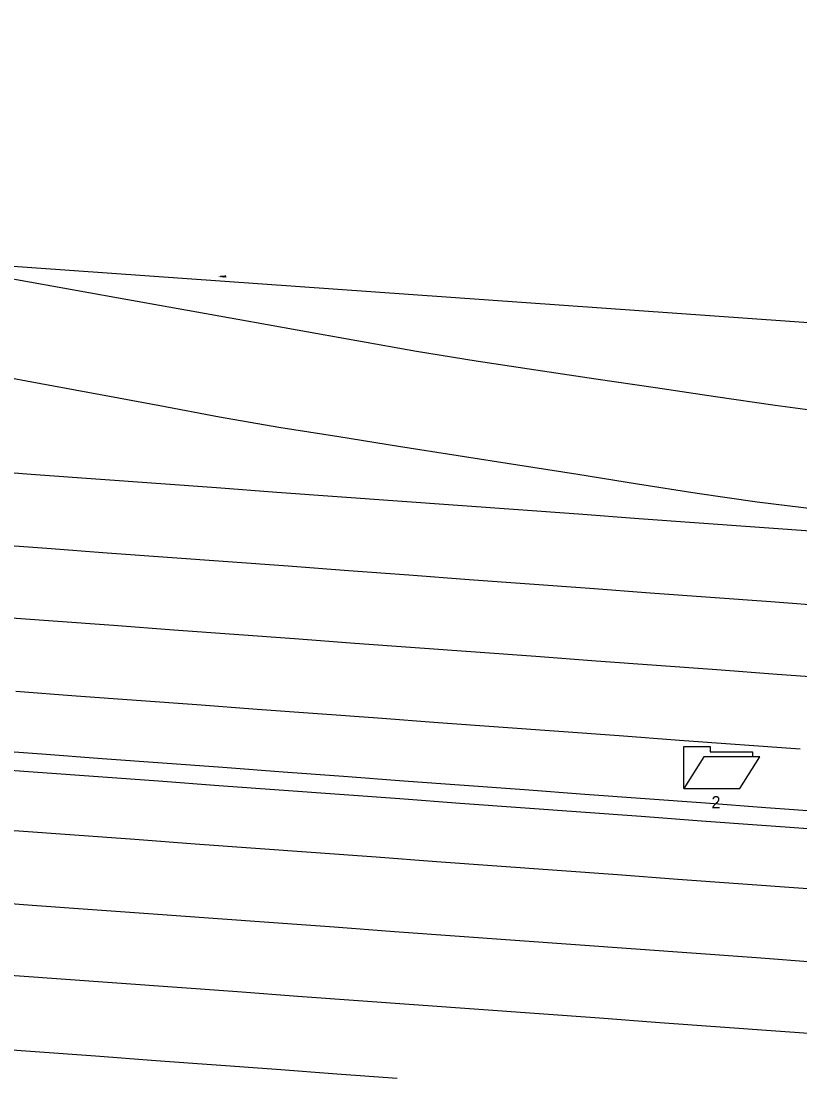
# Model space of a CAD drawing. Extents: x 1981993 to 1984113, y 708143 to 709490.
# Drawn here: x 1982674.4 to 1982803.2, y 708893.5 to 709067.8 of the extents above; entities that cross this region are included whole.
import ezdxf

# ---------------------------------------------------------------- set-up
doc = ezdxf.new("R2010")
doc.units = 0
for name, color, linetype in [('GE_X_Alignment_1000_Curve_Data', 7, 'Continuous'), ('GE_X_Alignment_1000_Distances', 7, 'Continuous'), ('GE_X_Alignment_100_Curve_Data', 7, 'Continuous'), ('GE_X_Alignment_100_Distances', 7, 'Continuous'), ('GE_X_Alignment_100_Stations', 7, 'Continuous'), ('GE_X_Alignment_500_Bearings', 7, 'Continuous'), ('GE_X_Alignment_500_Cardinal_Points', 7, 'Continuous'), ('GE_X_Alignment_500_Distances', 7, 'Continuous'), ('Scan Positions', 7, 'Continuous'), ('SV_P_Control_Cells_Set', 7, 'Continuous'), ('XS_X_Ground_Line', 7, 'Continuous')]:
    doc.layers.add(name, color=color, linetype=linetype)

msp = doc.modelspace()

# ---------------------------------------------------------------- linework, layer by layer
at = {"layer": 'GE_X_Alignment_1000_Curve_Data'}
for points in [[(1982808.34, 708971.06), (1982798.37, 708971.79), (1982788.4, 708972.53), (1982778.42, 708973.26), (1982768.45, 708973.99), (1982758.48, 708974.73), (1982748.5, 708975.46), (1982738.53, 708976.2), (1982728.56, 708976.93), (1982718.58, 708977.67), (1982708.61, 708978.4), (1982698.64, 708979.13), (1982688.67, 708979.87), (1982678.69, 708980.6), (1982668.72, 708981.34)], [(1982809.35, 708959.09), (1982799.38, 708959.82), (1982789.41, 708960.55), (1982779.44, 708961.28), (1982769.46, 708962.01), (1982759.49, 708962.75), (1982749.52, 708963.48), (1982739.54, 708964.21), (1982729.57, 708964.94), (1982719.6, 708965.67), (1982709.62, 708966.41), (1982699.65, 708967.14), (1982689.68, 708967.87), (1982679.7, 708968.6), (1982669.73, 708969.33)], [(1982666.31, 708922.44), (1982676.28, 708921.71), (1982686.25, 708920.99), (1982696.23, 708920.26), (1982706.2, 708919.54), (1982716.17, 708918.81), (1982726.15, 708918.09), (1982736.12, 708917.36), (1982746.1, 708916.64), (1982756.07, 708915.91), (1982766.04, 708915.19), (1982776.02, 708914.46), (1982785.99, 708913.74), (1982795.96, 708913.02), (1982805.94, 708912.29)], [(1982670.29, 708910.3), (1982680.27, 708909.58), (1982690.24, 708908.85), (1982700.21, 708908.13), (1982710.19, 708907.4), (1982720.16, 708906.68), (1982730.13, 708905.95), (1982740.11, 708905.23), (1982750.08, 708904.5), (1982760.05, 708903.78), (1982770.03, 708903.05), (1982780, 708902.33), (1982789.98, 708901.6), (1982799.95, 708900.88), (1982809.92, 708900.15)]]:
    msp.add_lwpolyline(points, dxfattribs=at)
at = {"layer": 'GE_X_Alignment_100_Curve_Data'}
msp.add_line((1982707.46, 709025.56), (1982707.46, 709025.56), dxfattribs=at)
for points in [[(1982707.67, 709025.48), (1982707.67, 709025.64), (1982707.72, 709025.48), (1982707.77, 709025.64), (1982707.77, 709025.48)], [(1982707.85, 709025.51), (1982707.85, 709025.51), (1982707.86, 709025.5), (1982707.86, 709025.5), (1982707.86, 709025.49), (1982707.86, 709025.49), (1982707.85, 709025.48), (1982707.85, 709025.48), (1982707.84, 709025.49), (1982707.84, 709025.49), (1982707.84, 709025.5), (1982707.84, 709025.5), (1982707.85, 709025.51)], [(1982707.91, 709025.48), (1982707.91, 709025.64), (1982707.99, 709025.48), (1982707.99, 709025.64)], [(1982708.07, 709025.51), (1982708.07, 709025.51), (1982708.08, 709025.5), (1982708.08, 709025.5), (1982708.08, 709025.49), (1982708.08, 709025.49), (1982708.07, 709025.48), (1982708.07, 709025.48), (1982708.06, 709025.49), (1982708.06, 709025.49), (1982708.06, 709025.5), (1982708.06, 709025.5), (1982708.07, 709025.51)], [(1982708.2, 709025.63), (1982708.2, 709025.64), (1982708.2, 709025.64), (1982708.19, 709025.64), (1982708.18, 709025.64), (1982708.17, 709025.64), (1982708.16, 709025.64), (1982708.15, 709025.64), (1982708.14, 709025.63), (1982708.13, 709025.62), (1982708.13, 709025.61), (1982708.13, 709025.61), (1982708.13, 709025.6), (1982708.14, 709025.59), (1982708.2, 709025.55), (1982708.21, 709025.54), (1982708.21, 709025.54), (1982708.21, 709025.53), (1982708.21, 709025.52), (1982708.21, 709025.52), (1982708.21, 709025.51), (1982708.21, 709025.51), (1982708.2, 709025.5), (1982708.2, 709025.5), (1982708.2, 709025.49), (1982708.19, 709025.49), (1982708.19, 709025.49), (1982708.19, 709025.49), (1982708.18, 709025.48), (1982708.16, 709025.48), (1982708.15, 709025.49), (1982708.14, 709025.5), (1982708.13, 709025.5)], [(1982708.29, 709025.51), (1982708.29, 709025.51), (1982708.3, 709025.5), (1982708.3, 709025.5), (1982708.3, 709025.49), (1982708.3, 709025.49), (1982708.29, 709025.48), (1982708.29, 709025.48), (1982708.28, 709025.49), (1982708.28, 709025.49), (1982708.28, 709025.5), (1982708.28, 709025.5), (1982708.29, 709025.51)]]:
    msp.add_lwpolyline(points, dxfattribs=at)
msp.add_circle((1982707.46, 709025.56), 0.0497, dxfattribs=at)
at = {"layer": 'GE_X_Alignment_100_Distances'}
for points in [[(1982807.49, 708937.05), (1982797.52, 708937.78), (1982787.54, 708938.52), (1982777.57, 708939.26), (1982767.6, 708939.99), (1982757.62, 708940.73), (1982747.65, 708941.46), (1982737.68, 708942.2), (1982727.71, 708942.94), (1982717.73, 708943.67), (1982707.76, 708944.41), (1982697.79, 708945.14), (1982687.81, 708945.88), (1982677.84, 708946.61), (1982667.87, 708947.35)], [(1982667.23, 708944.39), (1982677.21, 708943.66), (1982687.18, 708942.93), (1982697.15, 708942.21), (1982707.13, 708941.48), (1982717.1, 708940.75), (1982727.07, 708940.02), (1982737.05, 708939.29), (1982747.02, 708938.56), (1982756.99, 708937.83), (1982766.97, 708937.1), (1982776.94, 708936.37), (1982786.91, 708935.64), (1982796.89, 708934.91), (1982806.86, 708934.19)]]:
    msp.add_lwpolyline(points, dxfattribs=at)
at = {"layer": 'GE_X_Alignment_100_Stations'}
for points in [[(1982803.21, 708947.44), (1982793.24, 708948.17), (1982783.26, 708948.91), (1982773.29, 708949.64), (1982763.32, 708950.37), (1982753.34, 708951.11), (1982743.37, 708951.84), (1982733.4, 708952.57), (1982723.43, 708953.31), (1982713.45, 708954.04), (1982703.48, 708954.77), (1982693.51, 708955.51), (1982683.53, 708956.24), (1982673.56, 708956.97)], [(1982673.27, 708934.02), (1982683.24, 708933.29), (1982693.22, 708932.57), (1982703.19, 708931.84), (1982713.16, 708931.11), (1982723.14, 708930.38), (1982733.11, 708929.65), (1982743.08, 708928.92), (1982753.06, 708928.2), (1982763.03, 708927.47), (1982773, 708926.74), (1982782.98, 708926.01), (1982792.95, 708925.28), (1982802.92, 708924.55), (1982812.9, 708923.82)]]:
    msp.add_lwpolyline(points, dxfattribs=at)
at = {"layer": 'GE_X_Alignment_500_Bearings'}
msp.add_lwpolyline([(1982666.78, 708898.24), (1982676.75, 708897.51), (1982686.72, 708896.78), (1982696.7, 708896.05), (1982706.67, 708895.32), (1982716.64, 708894.59), (1982726.61, 708893.85), (1982736.59, 708893.12)], dxfattribs=at)
at = {"layer": 'GE_X_Alignment_500_Cardinal_Points'}
for points in [[(1982670.86, 709025.55), (1982680.7, 709023.78), (1982690.54, 709022.02), (1982700.39, 709020.26), (1982710.23, 709018.49), (1982720.07, 709016.73), (1982729.92, 709014.97), (1982739.76, 709013.2), (1982749.63, 709011.62), (1982759.52, 709010.15), (1982769.41, 709008.67), (1982779.3, 709007.19), (1982789.2, 709005.72), (1982799.09, 709004.28), (1982809, 709002.96)], [(1982667.88, 709009.71), (1982677.71, 709007.88), (1982687.54, 709006.05), (1982697.38, 709004.22), (1982707.21, 709002.39), (1982717.05, 709000.66), (1982726.93, 708999.1), (1982736.81, 708997.54), (1982746.69, 708995.99), (1982756.56, 708994.43), (1982766.44, 708992.87), (1982776.32, 708991.32), (1982786.2, 708989.76), (1982796.09, 708988.33), (1982806.02, 708987.09), (1982815.94, 708985.85), (1982825.86, 708984.62), (1982835.78, 708983.38), (1982845.71, 708982.14), (1982855.63, 708980.9), (1982865.55, 708979.66), (1982875.47, 708978.42), (1982876.26, 708978.32)], [(1982666.81, 708993.59), (1982676.78, 708992.86), (1982686.76, 708992.13), (1982696.73, 708991.4), (1982706.71, 708990.68), (1982716.68, 708989.95), (1982726.65, 708989.22), (1982736.63, 708988.5), (1982746.6, 708987.77), (1982756.57, 708987.04), (1982766.55, 708986.32), (1982776.52, 708985.59), (1982786.49, 708984.86), (1982796.47, 708984.14), (1982806.44, 708983.41)]]:
    msp.add_lwpolyline(points, dxfattribs=at)
at = {"layer": 'Scan Positions'}
for points in [[(1982783.99, 708940.97), (1982783.99, 708947.89), (1982788.32, 708947.89), (1982788.32, 708947), (1982795.33, 708947), (1982795.33, 708946.19), (1982787.29, 708946.19)], [(1982783.99, 708940.97), (1982783.99, 708947.89), (1982788.32, 708947.89), (1982788.32, 708947), (1982795.33, 708947), (1982795.33, 708946.19), (1982787.29, 708946.19)], [(1982783.99, 708940.97), (1982783.99, 708947.89), (1982788.32, 708947.89), (1982788.32, 708947), (1982795.33, 708947), (1982795.33, 708946.19), (1982787.29, 708946.19)], [(1982783.99, 708940.97), (1982793.24, 708940.97), (1982796.53, 708946.19), (1982787.29, 708946.19)], [(1982783.99, 708940.97), (1982793.24, 708940.97), (1982796.53, 708946.19), (1982787.29, 708946.19)], [(1982783.99, 708940.97), (1982793.24, 708940.97), (1982796.53, 708946.19), (1982787.29, 708946.19)]]:
    msp.add_lwpolyline(points, close=True, dxfattribs=at)
at = {"layer": 'XS_X_Ground_Line'}
msp.add_lwpolyline([(1982663.67, 709027.92), (1982807.73, 709017.75), (1982809.65, 709028.09), (1982810.36, 709035.73), (1982810.24, 709039.53), (1982816.16, 709051.34), (1982820.07, 709063.16), (1982819.25, 709067.75), (1982918.34, 709060.55), (1982984.18, 709055.71), (1983016.51, 709027.82), (1983014.74, 709019.32), (1983015.34, 709014.34), (1983007.48, 709009.38), (1983004.16, 708999.5), (1982992.13, 708982.69), (1983030.35, 708979.95)], dxfattribs=at)

# ---------------------------------------------------------------- texts
at = {"layer": 'GE_X_Alignment_1000_Distances'}
msp.add_text('911.008', height=0.1, dxfattribs=at).set_placement((1982706.97, 709025.46))
at = {"layer": 'GE_X_Alignment_500_Distances'}
msp.add_text('CNPT12', height=0.1, dxfattribs=at).set_placement((1982706.92, 709025.56))
at = {"layer": 'Scan Positions'}
msp.add_text('2', height=2, dxfattribs=at).set_placement((1982788.54, 708937.7))
msp.add_text('2', height=2, dxfattribs=at).set_placement((1982788.54, 708937.7))
msp.add_text('2', height=2, dxfattribs=at).set_placement((1982788.54, 708937.7))
at = {"layer": 'SV_P_Control_Cells_Set'}
msp.add_text('MAGS', height=0.1, dxfattribs=at).set_placement((1982707.46, 709025.46))

doc.saveas('drawing.dxf')
